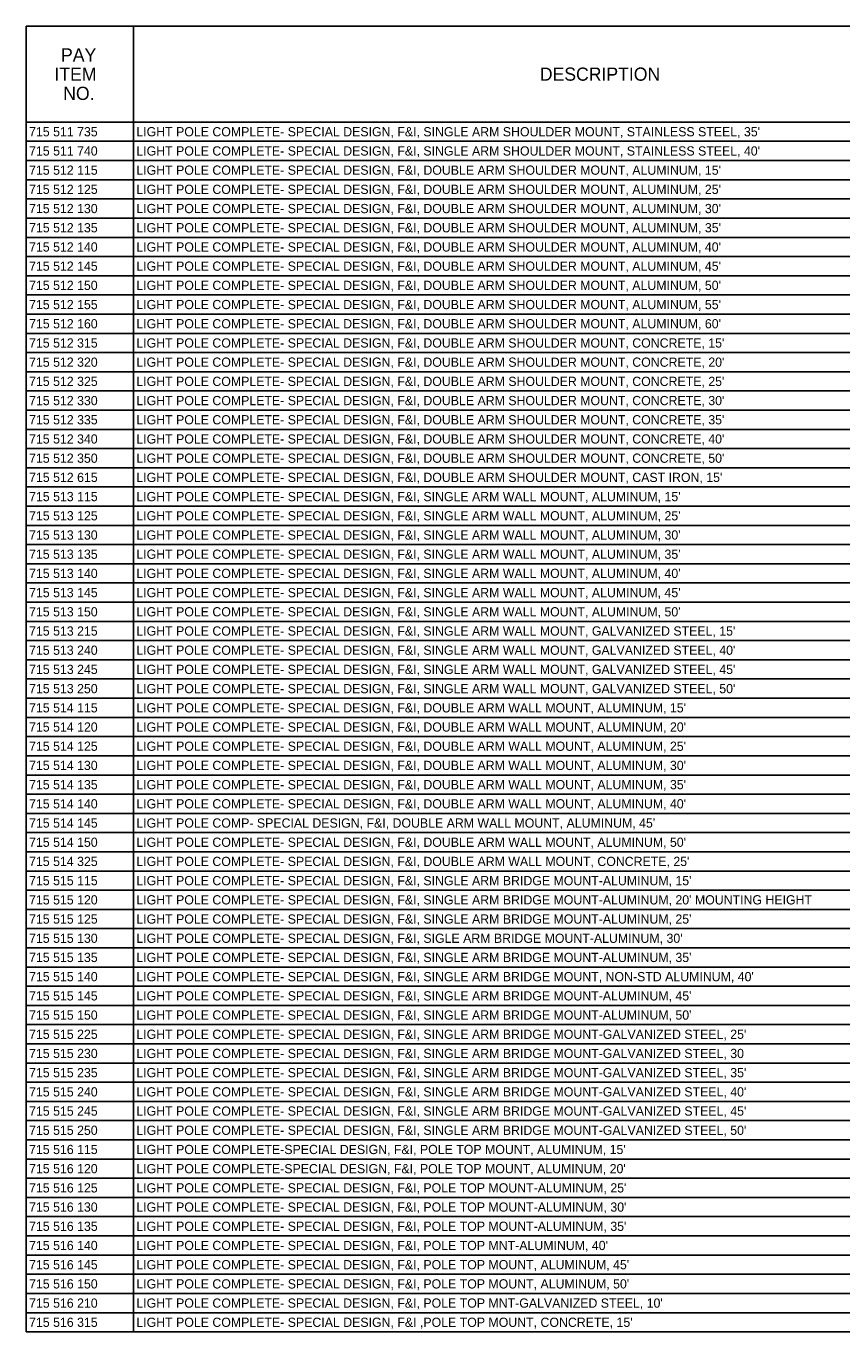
# Model space of a CAD drawing. Extents: x 56 to 1513, y -69 to 5602.
# Drawn here: x 56 to 598, y 2393 to 3260 of the extents above; entities that cross this region are included whole.
import ezdxf

# ---------------------------------------------------------------- set-up
doc = ezdxf.new("R2010")
doc.units = 0
for name, color, linetype in [('SheetLines_dp', 7, 'Continuous'), ('TextCurveData', 7, 'Continuous'), ('TextMinor', 7, 'Continuous'), ('TextMisc', 7, 'Continuous')]:
    doc.layers.add(name, color=color, linetype=linetype)

msp = doc.modelspace()

# ---------------------------------------------------------------- linework, layer by layer
at = {"layer": 'SheetLines_dp'}
for p, q in [((55.84, 3260.27), (55.84, 2393.27)), ((127.09, 3260.27), (127.09, 2393.27)), ((127.09, 3260.27), (127.09, 2393.27)), ((55.84, 3196.52), (1483.84, 3196.52)), ((55.84, 2393.27), (1483.84, 2393.27))]:
    msp.add_line(p, q, dxfattribs=at)
at = {"layer": 'TextMinor'}
for q in [(1431.34, 3260.27), (1483.84, 3260.27)]:
    msp.add_line((55.84, 3260.27), q, dxfattribs=at)
at = {"layer": 'TextMisc'}
for p, q in [((55.84, 3196.52), (1221.34, 3196.52)), ((55.84, 3183.77), (1221.34, 3183.77)), ((55.84, 3183.77), (1221.34, 3183.77)), ((55.84, 3171.02), (1221.34, 3171.02)), ((55.84, 3171.02), (1221.34, 3171.02)), ((55.84, 3158.27), (1221.34, 3158.27)), ((55.84, 3158.27), (1221.34, 3158.27)), ((55.84, 3145.52), (1221.34, 3145.52)), ((55.84, 3145.52), (1221.34, 3145.52)), ((55.84, 3132.77), (1221.34, 3132.77)), ((55.84, 3132.77), (1221.34, 3132.77)), ((55.84, 3120.02), (1221.34, 3120.02)), ((55.84, 3120.02), (1221.34, 3120.02)), ((55.84, 3107.27), (1221.34, 3107.27)), ((55.84, 3107.27), (1221.34, 3107.27)), ((55.84, 3094.52), (1221.34, 3094.52)), ((55.84, 3094.52), (1221.34, 3094.52)), ((55.84, 3081.77), (1221.34, 3081.77)), ((55.84, 3081.77), (1221.34, 3081.77)), ((55.84, 3069.02), (1221.34, 3069.02)), ((55.84, 3069.02), (1221.34, 3069.02)), ((55.84, 3056.27), (1221.34, 3056.27)), ((55.84, 3056.27), (1221.34, 3056.27)), ((55.84, 3043.52), (1221.34, 3043.52)), ((55.84, 3043.52), (1221.34, 3043.52)), ((55.84, 3030.77), (1221.34, 3030.77)), ((55.84, 3030.77), (1221.34, 3030.77)), ((55.84, 3018.02), (1221.34, 3018.02)), ((55.84, 3018.02), (1221.34, 3018.02)), ((55.84, 3005.27), (1221.34, 3005.27)), ((55.84, 3005.27), (1221.34, 3005.27)), ((55.84, 2992.52), (1221.34, 2992.52)), ((55.84, 2992.52), (1221.34, 2992.52)), ((55.84, 2979.77), (1221.34, 2979.77)), ((55.84, 2979.77), (1221.34, 2979.77)), ((55.84, 2967.02), (1221.34, 2967.02)), ((55.84, 2967.02), (1221.34, 2967.02)), ((55.84, 2954.27), (1221.34, 2954.27)), ((55.84, 2954.27), (1221.34, 2954.27)), ((55.84, 2941.52), (1221.34, 2941.52)), ((55.84, 2941.52), (1221.34, 2941.52)), ((55.84, 2928.77), (1221.34, 2928.77)), ((55.84, 2928.77), (1221.34, 2928.77)), ((55.84, 2916.02), (1221.34, 2916.02)), ((55.84, 2916.02), (1221.34, 2916.02)), ((55.84, 2903.27), (1221.34, 2903.27)), ((55.84, 2903.27), (1221.34, 2903.27)), ((55.84, 2890.52), (1221.34, 2890.52)), ((55.84, 2890.52), (1221.34, 2890.52)), ((55.84, 2877.77), (1221.34, 2877.77)), ((55.84, 2877.77), (1221.34, 2877.77)), ((55.84, 2865.02), (1221.34, 2865.02)), ((55.84, 2865.02), (1221.34, 2865.02)), ((55.84, 2852.27), (1221.34, 2852.27)), ((55.84, 2852.27), (1221.34, 2852.27)), ((55.84, 2839.52), (1221.34, 2839.52)), ((55.84, 2839.52), (1221.34, 2839.52)), ((55.84, 2826.77), (1221.34, 2826.77)), ((55.84, 2826.77), (1221.34, 2826.77)), ((55.84, 2814.02), (1221.34, 2814.02)), ((55.84, 2814.02), (1221.34, 2814.02)), ((55.84, 2801.27), (1221.34, 2801.27)), ((55.84, 2801.27), (1221.34, 2801.27)), ((55.84, 2788.52), (1221.34, 2788.52)), ((55.84, 2788.52), (1221.34, 2788.52)), ((55.84, 2775.77), (1221.34, 2775.77)), ((55.84, 2775.77), (1221.34, 2775.77)), ((55.84, 2763.02), (1221.34, 2763.02)), ((55.84, 2763.02), (1221.34, 2763.02)), ((55.84, 2750.27), (1221.34, 2750.27)), ((55.84, 2750.27), (1221.34, 2750.27)), ((55.84, 2737.52), (1221.34, 2737.52)), ((55.84, 2737.52), (1221.34, 2737.52)), ((55.84, 2724.77), (1221.34, 2724.77)), ((55.84, 2724.77), (1221.34, 2724.77)), ((55.84, 2712.02), (1221.34, 2712.02)), ((55.84, 2712.02), (1221.34, 2712.02)), ((55.84, 2699.27), (1221.34, 2699.27)), ((55.84, 2699.27), (1221.34, 2699.27)), ((55.84, 2686.52), (1221.34, 2686.52)), ((55.84, 2686.52), (1221.34, 2686.52)), ((55.84, 2673.77), (1221.34, 2673.77)), ((55.84, 2673.77), (1221.34, 2673.77)), ((55.84, 2661.02), (1221.34, 2661.02)), ((55.84, 2661.02), (1221.34, 2661.02)), ((55.84, 2648.27), (1221.34, 2648.27)), ((55.84, 2648.27), (1221.34, 2648.27)), ((55.84, 2635.52), (1221.34, 2635.52)), ((55.84, 2635.52), (1221.34, 2635.52)), ((55.84, 2622.77), (1221.34, 2622.77)), ((55.84, 2622.77), (1221.34, 2622.77)), ((55.84, 2610.02), (1221.34, 2610.02)), ((55.84, 2610.02), (1221.34, 2610.02)), ((55.84, 2597.27), (1221.34, 2597.27)), ((55.84, 2597.27), (1221.34, 2597.27)), ((55.84, 2584.52), (1221.34, 2584.52)), ((55.84, 2584.52), (1221.34, 2584.52)), ((55.84, 2571.77), (1221.34, 2571.77)), ((55.84, 2571.77), (1221.34, 2571.77)), ((55.84, 2559.02), (1221.34, 2559.02)), ((55.84, 2559.02), (1221.34, 2559.02)), ((55.84, 2546.27), (1221.34, 2546.27)), ((55.84, 2546.27), (1221.34, 2546.27)), ((55.84, 2533.52), (1221.34, 2533.52)), ((55.84, 2533.52), (1221.34, 2533.52)), ((55.84, 2520.77), (1221.34, 2520.77)), ((55.84, 2520.77), (1221.34, 2520.77)), ((55.84, 2508.02), (1221.34, 2508.02)), ((55.84, 2508.02), (1221.34, 2508.02)), ((55.84, 2495.27), (1221.34, 2495.27)), ((55.84, 2495.27), (1221.34, 2495.27)), ((55.84, 2482.52), (1221.34, 2482.52)), ((55.84, 2482.52), (1221.34, 2482.52)), ((55.84, 2469.77), (1221.34, 2469.77)), ((55.84, 2469.77), (1221.34, 2469.77)), ((55.84, 2457.02), (1221.34, 2457.02)), ((55.84, 2457.02), (1221.34, 2457.02)), ((55.84, 2444.27), (1221.34, 2444.27)), ((55.84, 2444.27), (1221.34, 2444.27)), ((55.84, 2431.52), (1221.34, 2431.52)), ((55.84, 2431.52), (1221.34, 2431.52)), ((55.84, 2418.77), (1221.34, 2418.77)), ((55.84, 2418.77), (1221.34, 2418.77)), ((55.84, 2406.02), (1221.34, 2406.02)), ((55.84, 2406.02), (1221.34, 2406.02))]:
    msp.add_line(p, q, dxfattribs=at)

# ---------------------------------------------------------------- texts
at = {"layer": 'TextCurveData'}
for s, height, p in [('PAY', 8.75, (79.05, 3236.77)), ('ITEM', 8.75, (74.66, 3224.02)), ('DESCRIPTION', 8.75, (397.17, 3224.02)), ('NO.', 8.75, (80.51, 3211.27)), ('715 511 735', 6.125, (57.84, 3187.08)), ("LIGHT POLE COMPLETE- SPECIAL DESIGN, F&I, SINGLE ARM SHOULDER MOUNT, STAINLESS STEEL, 35'", 6.125, (129.09, 3187.08)), ('715 511 740', 6.125, (57.84, 3174.33)), ("LIGHT POLE COMPLETE- SPECIAL DESIGN, F&I, SINGLE ARM SHOULDER MOUNT, STAINLESS STEEL, 40'", 6.125, (129.09, 3174.33)), ('715 512 115', 6.125, (57.84, 3161.58)), ("LIGHT POLE COMPLETE- SPECIAL DESIGN, F&I, DOUBLE ARM SHOULDER MOUNT, ALUMINUM, 15'", 6.125, (129.09, 3161.58)), ('715 512 125', 6.125, (57.84, 3148.83)), ("LIGHT POLE COMPLETE- SPECIAL DESIGN, F&I, DOUBLE ARM SHOULDER MOUNT, ALUMINUM, 25'", 6.125, (129.09, 3148.83)), ('715 512 130', 6.125, (57.84, 3136.08)), ("LIGHT POLE COMPLETE- SPECIAL DESIGN, F&I, DOUBLE ARM SHOULDER MOUNT, ALUMINUM, 30'", 6.125, (129.09, 3136.08)), ('715 512 135', 6.125, (57.84, 3123.33)), ("LIGHT POLE COMPLETE- SPECIAL DESIGN, F&I, DOUBLE ARM SHOULDER MOUNT, ALUMINUM, 35'", 6.125, (129.09, 3123.33)), ('715 512 140', 6.125, (57.84, 3110.58)), ("LIGHT POLE COMPLETE- SPECIAL DESIGN, F&I, DOUBLE ARM SHOULDER MOUNT, ALUMINUM, 40'", 6.125, (129.09, 3110.58)), ('715 512 145', 6.125, (57.84, 3097.83)), ("LIGHT POLE COMPLETE- SPECIAL DESIGN, F&I, DOUBLE ARM SHOULDER MOUNT, ALUMINUM, 45'", 6.125, (129.09, 3097.83)), ('715 512 150', 6.125, (57.84, 3085.08)), ("LIGHT POLE COMPLETE- SPECIAL DESIGN, F&I, DOUBLE ARM SHOULDER MOUNT, ALUMINUM, 50'", 6.125, (129.09, 3085.08)), ('715 512 155', 6.125, (57.84, 3072.33)), ("LIGHT POLE COMPLETE- SPECIAL DESIGN, F&I, DOUBLE ARM SHOULDER MOUNT, ALUMINUM, 55'", 6.125, (129.09, 3072.33)), ('715 512 160', 6.125, (57.84, 3059.58)), ("LIGHT POLE COMPLETE- SPECIAL DESIGN, F&I, DOUBLE ARM SHOULDER MOUNT, ALUMINUM, 60'", 6.125, (129.09, 3059.58)), ('715 512 315', 6.125, (57.84, 3046.83)), ("LIGHT POLE COMPLETE- SPECIAL DESIGN, F&I, DOUBLE ARM SHOULDER MOUNT, CONCRETE, 15'", 6.125, (129.09, 3046.83)), ('715 512 320', 6.125, (57.84, 3034.08)), ("LIGHT POLE COMPLETE- SPECIAL DESIGN, F&I, DOUBLE ARM SHOULDER MOUNT, CONCRETE, 20'", 6.125, (129.09, 3034.08)), ('715 512 325', 6.125, (57.84, 3021.33)), ("LIGHT POLE COMPLETE- SPECIAL DESIGN, F&I, DOUBLE ARM SHOULDER MOUNT, CONCRETE, 25'", 6.125, (129.09, 3021.33)), ('715 512 330', 6.125, (57.84, 3008.58)), ("LIGHT POLE COMPLETE- SPECIAL DESIGN, F&I, DOUBLE ARM SHOULDER MOUNT, CONCRETE, 30'", 6.125, (129.09, 3008.58)), ('715 512 335', 6.125, (57.84, 2995.83)), ("LIGHT POLE COMPLETE- SPECIAL DESIGN, F&I, DOUBLE ARM SHOULDER MOUNT, CONCRETE, 35'", 6.125, (129.09, 2995.83)), ('715 512 340', 6.125, (57.84, 2983.08)), ("LIGHT POLE COMPLETE- SPECIAL DESIGN, F&I, DOUBLE ARM SHOULDER MOUNT, CONCRETE, 40'", 6.125, (129.09, 2983.08)), ('715 512 350', 6.125, (57.84, 2970.33)), ("LIGHT POLE COMPLETE- SPECIAL DESIGN, F&I, DOUBLE ARM SHOULDER MOUNT, CONCRETE, 50'", 6.125, (129.09, 2970.33)), ('715 512 615', 6.125, (57.84, 2957.58)), ("LIGHT POLE COMPLETE- SPECIAL DESIGN, F&I, DOUBLE ARM SHOULDER MOUNT, CAST IRON, 15'", 6.125, (129.09, 2957.58)), ('715 513 115', 6.125, (57.84, 2944.83)), ("LIGHT POLE COMPLETE- SPECIAL DESIGN, F&I, SINGLE ARM WALL MOUNT, ALUMINUM, 15'", 6.125, (129.09, 2944.83)), ('715 513 125', 6.125, (57.84, 2932.08)), ("LIGHT POLE COMPLETE- SPECIAL DESIGN, F&I, SINGLE ARM WALL MOUNT, ALUMINUM, 25'", 6.125, (129.09, 2932.08)), ('715 513 130', 6.125, (57.84, 2919.33)), ("LIGHT POLE COMPLETE- SPECIAL DESIGN, F&I, SINGLE ARM WALL MOUNT, ALUMINUM, 30'", 6.125, (129.09, 2919.33)), ('715 513 135', 6.125, (57.84, 2906.58)), ("LIGHT POLE COMPLETE- SPECIAL DESIGN, F&I, SINGLE ARM WALL MOUNT, ALUMINUM, 35'", 6.125, (129.09, 2906.58)), ('715 513 140', 6.125, (57.84, 2893.83)), ("LIGHT POLE COMPLETE- SPECIAL DESIGN, F&I, SINGLE ARM WALL MOUNT, ALUMINUM, 40'", 6.125, (129.09, 2893.83)), ('715 513 145', 6.125, (57.84, 2881.08)), ("LIGHT POLE COMPLETE- SPECIAL DESIGN, F&I, SINGLE ARM WALL MOUNT, ALUMINUM, 45'", 6.125, (129.09, 2881.08)), ('715 513 150', 6.125, (57.84, 2868.33)), ("LIGHT POLE COMPLETE- SPECIAL DESIGN, F&I, SINGLE ARM WALL MOUNT, ALUMINUM, 50'", 6.125, (129.09, 2868.33)), ('715 513 215', 6.125, (57.84, 2855.58)), ("LIGHT POLE COMPLETE- SPECIAL DESIGN, F&I, SINGLE ARM WALL MOUNT, GALVANIZED STEEL, 15'", 6.125, (129.09, 2855.58)), ('715 513 240', 6.125, (57.84, 2842.83)), ("LIGHT POLE COMPLETE- SPECIAL DESIGN, F&I, SINGLE ARM WALL MOUNT, GALVANIZED STEEL, 40'", 6.125, (129.09, 2842.83)), ('715 513 245', 6.125, (57.84, 2830.08)), ("LIGHT POLE COMPLETE- SPECIAL DESIGN, F&I, SINGLE ARM WALL MOUNT, GALVANIZED STEEL, 45'", 6.125, (129.09, 2830.08)), ('715 513 250', 6.125, (57.84, 2817.33)), ("LIGHT POLE COMPLETE- SPECIAL DESIGN, F&I, SINGLE ARM WALL MOUNT, GALVANIZED STEEL, 50'", 6.125, (129.09, 2817.33)), ('715 514 115', 6.125, (57.84, 2804.58)), ("LIGHT POLE COMPLETE- SPECIAL DESIGN, F&I, DOUBLE ARM WALL MOUNT, ALUMINUM, 15'", 6.125, (129.09, 2804.58)), ('715 514 120', 6.125, (57.84, 2791.83)), ("LIGHT POLE COMPLETE- SPECIAL DESIGN, F&I, DOUBLE ARM WALL MOUNT, ALUMINUM, 20'", 6.125, (129.09, 2791.83)), ('715 514 125', 6.125, (57.84, 2779.08)), ("LIGHT POLE COMPLETE- SPECIAL DESIGN, F&I, DOUBLE ARM WALL MOUNT, ALUMINUM, 25'", 6.125, (129.09, 2779.08)), ('715 514 130', 6.125, (57.84, 2766.33)), ("LIGHT POLE COMPLETE- SPECIAL DESIGN, F&I, DOUBLE ARM WALL MOUNT, ALUMINUM, 30'", 6.125, (129.09, 2766.33)), ('715 514 135', 6.125, (57.84, 2753.58)), ("LIGHT POLE COMPLETE- SPECIAL DESIGN, F&I, DOUBLE ARM WALL MOUNT, ALUMINUM, 35'", 6.125, (129.09, 2753.58)), ('715 514 140', 6.125, (57.84, 2740.83)), ("LIGHT POLE COMPLETE- SPECIAL DESIGN, F&I, DOUBLE ARM WALL MOUNT, ALUMINUM, 40'", 6.125, (129.09, 2740.83)), ('715 514 145', 6.125, (57.84, 2728.08)), ("LIGHT POLE COMP- SPECIAL DESIGN, F&I, DOUBLE ARM WALL MOUNT, ALUMINUM, 45'", 6.125, (129.09, 2728.08)), ('715 514 150', 6.125, (57.84, 2715.33)), ("LIGHT POLE COMPLETE- SPECIAL DESIGN, F&I, DOUBLE ARM WALL MOUNT, ALUMINUM, 50'", 6.125, (129.09, 2715.33)), ('715 514 325', 6.125, (57.84, 2702.58)), ("LIGHT POLE COMPLETE- SPECIAL DESIGN, F&I, DOUBLE ARM WALL MOUNT, CONCRETE, 25'", 6.125, (129.09, 2702.58)), ('715 515 115', 6.125, (57.84, 2689.83)), ("LIGHT POLE COMPLETE- SPECIAL DESIGN, F&I, SINGLE ARM BRIDGE MOUNT-ALUMINUM, 15'", 6.125, (129.09, 2689.83)), ('715 515 120', 6.125, (57.84, 2677.08)), ("LIGHT POLE COMPLETE- SPECIAL DESIGN, F&I, SINGLE ARM BRIDGE MOUNT-ALUMINUM, 20' MOUNTING HEIGHT", 6.125, (129.09, 2677.08)), ('715 515 125', 6.125, (57.84, 2664.33)), ("LIGHT POLE COMPLETE- SPECIAL DESIGN, F&I, SINGLE ARM BRIDGE MOUNT-ALUMINUM, 25'", 6.125, (129.09, 2664.33)), ('715 515 130', 6.125, (57.84, 2651.58)), ("LIGHT POLE COMPLETE- SPECIAL DESIGN, F&I, SIGLE ARM BRIDGE MOUNT-ALUMINUM, 30'", 6.125, (129.09, 2651.58)), ('715 515 135', 6.125, (57.84, 2638.83)), ("LIGHT POLE COMPLETE- SEPCIAL DESIGN, F&I, SINGLE ARM BRIDGE MOUNT-ALUMINUM, 35'", 6.125, (129.09, 2638.83)), ('715 515 140', 6.125, (57.84, 2626.08)), ("LIGHT POLE COMPLETE- SEPCIAL DESIGN, F&I, SINGLE ARM BRIDGE MOUNT, NON-STD ALUMINUM, 40'", 6.125, (129.09, 2626.08)), ('715 515 145', 6.125, (57.84, 2613.33)), ("LIGHT POLE COMPLETE- SPECIAL DESIGN, F&I, SINGLE ARM BRIDGE MOUNT-ALUMINUM, 45'", 6.125, (129.09, 2613.33)), ('715 515 150', 6.125, (57.84, 2600.58)), ("LIGHT POLE COMPLETE- SPECIAL DESIGN, F&I, SINGLE ARM BRIDGE MOUNT-ALUMINUM, 50'", 6.125, (129.09, 2600.58)), ('715 515 225', 6.125, (57.84, 2587.83)), ("LIGHT POLE COMPLETE- SPECIAL DESIGN, F&I, SINGLE ARM BRIDGE MOUNT-GALVANIZED STEEL, 25'", 6.125, (129.09, 2587.83)), ('715 515 230', 6.125, (57.84, 2575.08)), ('LIGHT POLE COMPLETE- SPECIAL DESIGN, F&I, SINGLE ARM BRIDGE MOUNT-GALVANIZED STEEL, 30', 6.125, (129.09, 2575.08)), ('715 515 235', 6.125, (57.84, 2562.33)), ("LIGHT POLE COMPLETE- SPECIAL DESIGN, F&I, SINGLE ARM BRIDGE MOUNT-GALVANIZED STEEL, 35'", 6.125, (129.09, 2562.33)), ('715 515 240', 6.125, (57.84, 2549.58)), ("LIGHT POLE COMPLETE- SPECIAL DESIGN, F&I, SINGLE ARM BRIDGE MOUNT-GALVANIZED STEEL, 40'", 6.125, (129.09, 2549.58)), ('715 515 245', 6.125, (57.84, 2536.83)), ("LIGHT POLE COMPLETE- SPECIAL DESIGN, F&I, SINGLE ARM BRIDGE MOUNT-GALVANIZED STEEL, 45'", 6.125, (129.09, 2536.83)), ('715 515 250', 6.125, (57.84, 2524.08)), ("LIGHT POLE COMPLETE- SPECIAL DESIGN, F&I, SINGLE ARM BRIDGE MOUNT-GALVANIZED STEEL, 50'", 6.125, (129.09, 2524.08)), ('715 516 115', 6.125, (57.84, 2511.33)), ("LIGHT POLE COMPLETE-SPECIAL DESIGN, F&I, POLE TOP MOUNT, ALUMINUM, 15'", 6.125, (129.09, 2511.33)), ('715 516 120', 6.125, (57.84, 2498.58)), ("LIGHT POLE COMPLETE-SPECIAL DESIGN, F&I, POLE TOP MOUNT, ALUMINUM, 20'", 6.125, (129.09, 2498.58)), ('715 516 125', 6.125, (57.84, 2485.83)), ("LIGHT POLE COMPLETE- SPECIAL DESIGN, F&I, POLE TOP MOUNT-ALUMINUM, 25'", 6.125, (129.09, 2485.83)), ('715 516 130', 6.125, (57.84, 2473.08)), ("LIGHT POLE COMPLETE- SPECIAL DESIGN, F&I, POLE TOP MOUNT-ALUMINUM, 30'", 6.125, (129.09, 2473.08)), ('715 516 135', 6.125, (57.84, 2460.33)), ("LIGHT POLE COMPLETE- SPECIAL DESIGN, F&I, POLE TOP MOUNT-ALUMINUM, 35'", 6.125, (129.09, 2460.33)), ('715 516 140', 6.125, (57.84, 2447.58)), ("LIGHT POLE COMPLETE- SPECIAL DESIGN, F&I, POLE TOP MNT-ALUMINUM, 40'", 6.125, (129.09, 2447.58)), ('715 516 145', 6.125, (57.84, 2434.83)), ("LIGHT POLE COMPLETE- SPECIAL DESIGN, F&I, POLE TOP MOUNT, ALUMINUM, 45'", 6.125, (129.09, 2434.83)), ('715 516 150', 6.125, (57.84, 2422.08)), ("LIGHT POLE COMPLETE- SPECIAL DESIGN, F&I, POLE TOP MOUNT, ALUMINUM, 50'", 6.125, (129.09, 2422.08)), ('715 516 210', 6.125, (57.84, 2409.33)), ("LIGHT POLE COMPLETE- SPECIAL DESIGN, F&I, POLE TOP MNT-GALVANIZED STEEL, 10'", 6.125, (129.09, 2409.33)), ('715 516 315', 6.125, (57.84, 2396.58)), ("LIGHT POLE COMPLETE- SPECIAL DESIGN, F&I ,POLE TOP MOUNT, CONCRETE, 15'", 6.125, (129.09, 2396.58))]:
    msp.add_text(s, height=height, dxfattribs=at).set_placement(p)

doc.saveas('drawing.dxf')
